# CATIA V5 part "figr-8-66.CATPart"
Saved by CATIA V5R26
Part number: Part1
Bounding box of the stored display mesh (mm): x -53.439 to 53.439, y -63.41 to 63.41, z -17.5 to 17.5
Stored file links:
  D:\_Deepak\CATIA\CATIA V5-6R2016_Deepak\Resources\Part files\Partfiles\c08_catia_v5_6r2016_prt\figr-8-66.CATPart
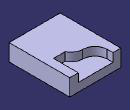
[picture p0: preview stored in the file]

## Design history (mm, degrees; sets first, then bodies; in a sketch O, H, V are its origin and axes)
Body1 (main body)
  Sketch1 on xy-plane, origin (0, 0, 0), H (1, 0, 0), V (0, 1, 0)
    line L1 (-53.4395, 63.4095) -> (53.4395, 63.4095)
    line L2 (53.4395, 63.4095) -> (53.4395, -63.4095)
    line L3 (53.4395, -63.4095) -> (-53.4395, -63.4095)
    line L4 (-53.4395, -63.4095) -> (-53.4395, 63.4095)
    axis line L5 (53.4395, -63.4095) -> (-53.4395, 63.4095)
    horizontal: L1 H, L3 H
    vertical: L2 V, L4 V
    midpoint: O L5
  Pad1: profile Sketch1, direction (0, 0, 1), length 17.5, mirrored extent
  Body2
    Sketch2 on xy-plane, origin (0, 0, 0), H (1, 0, 0), V (0, 1, 0)
      line L1 (-36.9238, 103.6333) -> (-36.9238, 51.4035)
      arc A1 centre (-11.4307, 51.4035) radius 25.4931 from (-36.9238, 51.4035) to (-11.4307, 25.9104) ccw
      arc A2 centre (-11.4307, 0.4172) radius 25.4931 from (-11.4307, 25.9104) to (11.4981, 11.5602) cw
      line L2 (11.4981, 11.5602) -> (35.6176, 11.5602)
      line L3 (35.6176, 11.5602) -> (35.6176, 103.6333)
      line L4 (35.6176, 103.6333) -> (-36.9238, 103.6333)
      vertical: L1 V, L3 V
      tangency: A1 L1, A2 L1, A2 A1
      horizontal: L2 H, L4 H
    Pad2: profile Sketch2, direction (0, 0, 1), length 34.5
  Remove1: tool Body2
